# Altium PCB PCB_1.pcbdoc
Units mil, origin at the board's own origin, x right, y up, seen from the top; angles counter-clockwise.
Board outline 1920 x 3860 mil, 2 copper layers (Top Layer, Bottom Layer); 60 components, 43 nets, 203 pads, 40 vias.
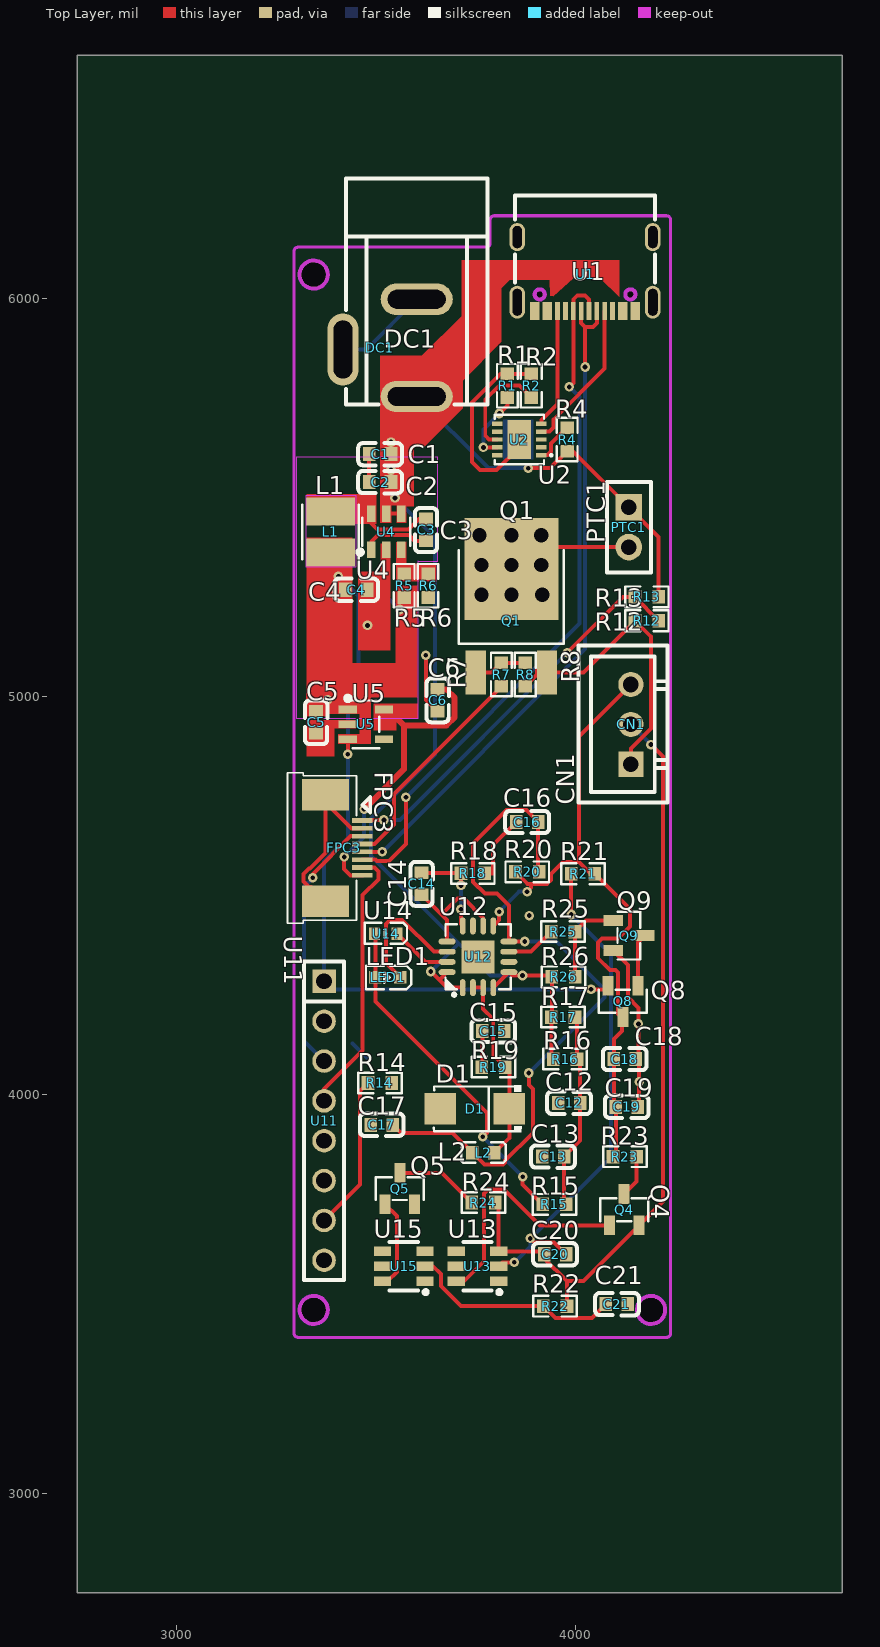
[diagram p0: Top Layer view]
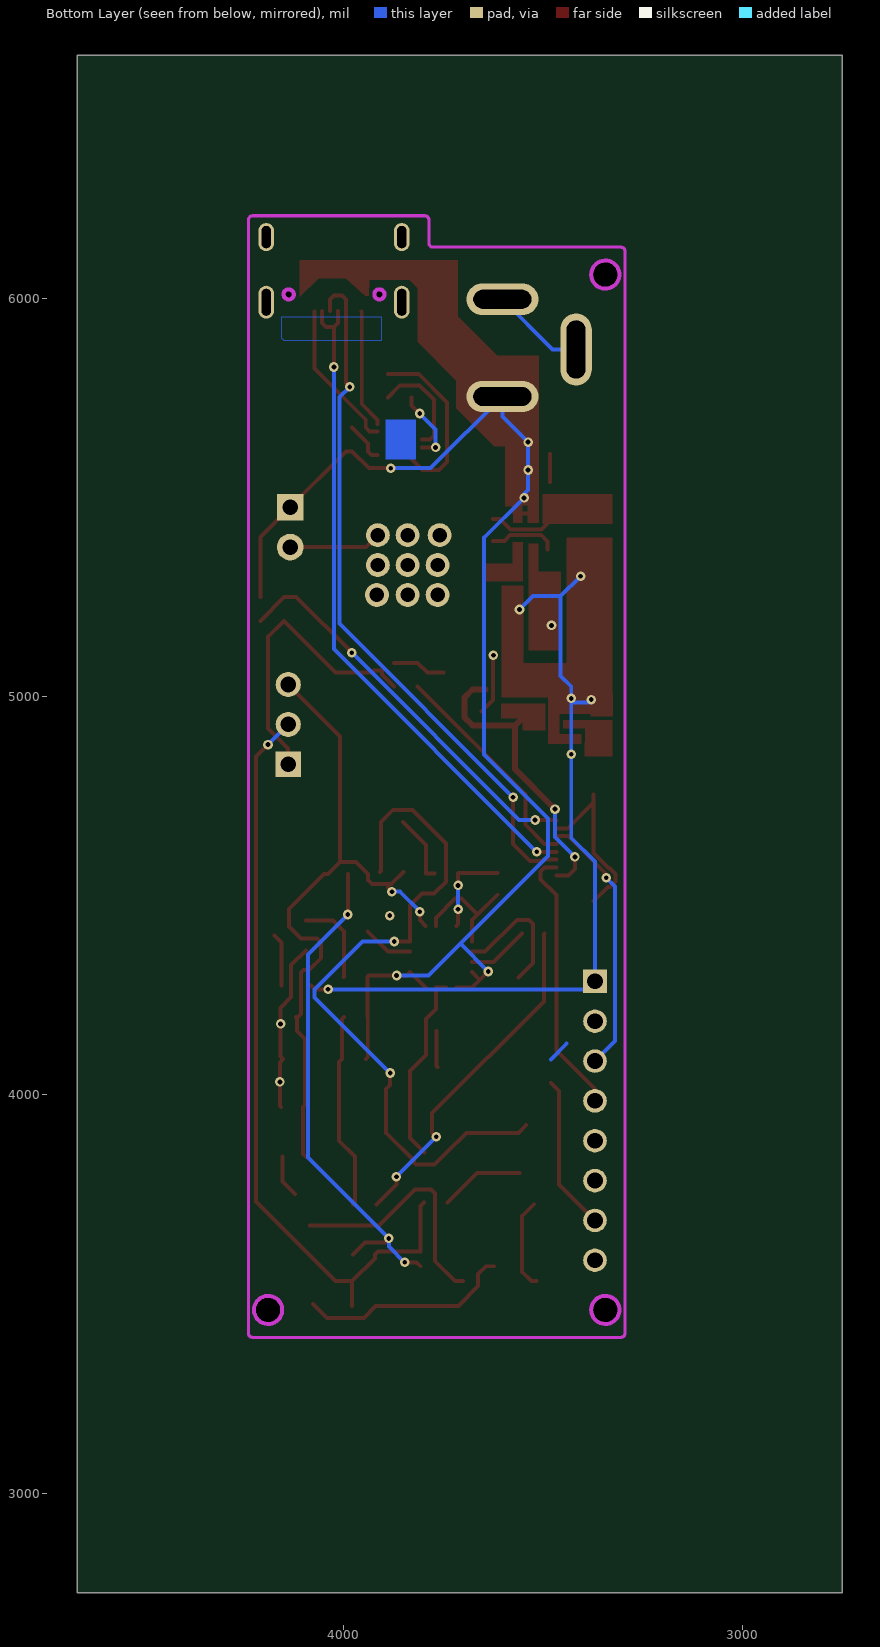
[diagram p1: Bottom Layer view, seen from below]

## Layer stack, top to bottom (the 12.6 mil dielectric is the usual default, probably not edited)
Top Layer: signal copper (thickness not stored)
Dielectric: dielectric 12.6, FR-4, Dk 4.8
Bottom Layer: signal copper (thickness not stored)

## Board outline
4670,2750 2750,2750 2750,6610 4670,6610
cut-out: 3379.43,6058.89 ccw(c3344,6058.67) 3308.57,6058.89 ccw(c3344,6059.11)
cut-out: 3379.43,3460.47 ccw(c3344,3460.25) 3308.57,3460.47 ccw(c3344,3460.69)
cut-out: 4225.89,3460.47 ccw(c4190.45,3460.47) 4155.02,3460.47 ccw(c4190.45,3460.47)

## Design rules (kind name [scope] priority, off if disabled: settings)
BoardOutlineClearance copperThickness1oz [All] p0: genericclearance=10 ignorepadtopadclearanceinfootprint=FALSE except(0: Arc-SplitContinuation Track-SplitContinuation SMDPad-SplitContinuation THPad-SplitContinuation Via-SplitContinuation Fill-SplitContinuation Poly-SplitContinuation Region-SplitContinuation Text-SplitContinuation; 6: Track-CutoutEdge SMDPad-CutoutEdge THPad-CutoutEdge Via-CutoutEdge Region-CutoutEdge; 11.8: Track-OutlineEdge SMDPad-OutlineEdge THPad-OutlineEdge Via-OutlineEdge Fill-OutlineEdge Region-OutlineEdge Poly-OutlineEdge Text-OutlineEdge Fill-CutoutEdge)
BoardOutlineClearance copperThickness2oz [All] p0: genericclearance=10 ignorepadtopadclearanceinfootprint=FALSE except(0: Arc-SplitContinuation Track-SplitContinuation SMDPad-SplitContinuation THPad-SplitContinuation Via-SplitContinuation Fill-SplitContinuation Poly-SplitContinuation Region-SplitContinuation Text-SplitContinuation; 6: Track-CutoutEdge SMDPad-CutoutEdge THPad-CutoutEdge Via-CutoutEdge Region-CutoutEdge; 11.8: Track-OutlineEdge SMDPad-OutlineEdge THPad-OutlineEdge Via-OutlineEdge Fill-OutlineEdge Region-OutlineEdge Poly-OutlineEdge Text-OutlineEdge Fill-CutoutEdge)
Clearance copperThickness1oz [(InNet('GND') OR InNet('3V3') OR InNet('ADC_VIN') OR InNet('$2N1457') OR InNet('$2N1458') OR InNet('VIN') OR InNet('5V') OR InNet('DN1') OR InNet('DP1') OR InNet('$2N173') OR InNet('$2N169') OR InNet('$2N860') OR InNet('$2N846') OR InNet('$2N1461') OR InNet('$2N861') OR InNet('CC1') OR InNet('CC2') OR InNet('PTC') OR InNet('SCL') OR InNet('SDA') OR InNet('AD0') OR InNet('XDA') OR InNet('XCL') OR InNet('INT') OR InNet('$2N25200') OR InNet('$2N24838') OR InNet('$2N25111') OR InNet('$2N25373') OR InNet('$2N25939') OR InNet('BAT+') OR InNet('$2N25975') OR InNet('$2N28041') OR InNet('$2N26224') OR InNet('$2N25852') OR InNet('$2N24540') OR InNet('$2N24753') OR InNet('$2N26433') OR InNet('$2N26509') OR InNet('$2N26582') OR InNet('$2N26578') OR InNet('$2N27775') OR InNet('$2N27867') OR InNet('$2N26613'))] p1: gap=7 ignorepadtopadclearanceinfootprint=FALSE except(4: Track-Track; 6: Track-SMDPad SMDPad-SMDPad Track-THPad SMDPad-THPad THPad-THPad Track-Via SMDPad-Via THPad-Via Via-Via SMDPad-Fill THPad-Fill Via-Fill Fill-Fill Track-Region SMDPad-Region THPad-Region Via-Region Region-Region Track-Poly SMDPad-Poly THPad-Poly Via-Poly Fill-Poly Region-Poly Poly-Poly Track-Text SMDPad-Text THPad-Text Via-Text Fill-Text Region-Text Poly-Text Text-Text; 6.9: Track-Hole SMDPad-Hole THPad-Hole Via-Hole Fill-Hole Region-Hole Poly-Hole Text-Hole Sheet-Hole; 11.8: Track-Fill Fill-Region Track-Sheet SMDPad-Sheet THPad-Sheet Via-Sheet Fill-Sheet Region-Sheet Poly-Sheet Text-Sheet)
Clearance copperThickness2oz [All] p1: gap=7 ignorepadtopadclearanceinfootprint=FALSE except(6: Track-SMDPad SMDPad-SMDPad Track-THPad SMDPad-THPad THPad-THPad Track-Via SMDPad-Via THPad-Via Via-Via SMDPad-Fill THPad-Fill Via-Fill Fill-Fill Track-Region SMDPad-Region THPad-Region Via-Region Region-Region Track-Poly SMDPad-Poly THPad-Poly Via-Poly Fill-Poly Region-Poly Poly-Poly Track-Text SMDPad-Text THPad-Text Via-Text Fill-Text Region-Text Poly-Text Text-Text; 6.9: Track-Hole SMDPad-Hole THPad-Hole Via-Hole Fill-Hole Region-Hole Poly-Hole Text-Hole Sheet-Hole; 8: Track-Track; 11.8: Track-Fill Fill-Region Track-Sheet SMDPad-Sheet THPad-Sheet Via-Sheet Fill-Sheet Region-Sheet Poly-Sheet Text-Sheet)
DiffPairsRouting differentialPair [All] p1: maxuncoupledlength=10 minlimit=6 maxlimit=6 mostfreqgap=6 toplayer_minwidth=5 toplayer_prefwidth=10 toplayer_maxwidth=100 bottomlayer_minwidth=5 bottomlayer_prefwidth=10 bottomlayer_maxwidth=100
PasteMaskExpansion pasteMaskExpansion [All] p1: expansion=0
PlaneConnect innerPlane [All] p1: planeconnectstyle=Relief reliefexpansion=20 reliefentries=4 reliefconductorwidth=10 reliefairgap=10
PolygonConnect copperRegion [All] p1: connectstyle=Relief reliefentries=4 reliefconductorwidth=10 polygonreliefangle="90 Angle" airgapwidth=10
RoutingVias viaSize [All] p1: viastyle="Through Hole" holewidth=12.0078 minholewidth=11.811 maxholewidth=248.0314 width=24.0158 minwidth=19.685 maxwidth=393.7008
SolderMaskExpansion solderMaskExpansion [All] p1: useseparateexpansions=TRUE expansion=2 expansionbottom=2
Width copperThickness1oz [All] p1: maxlimit=100 minlimit=5 preferedwidth=10
Width copperThickness2oz [All] p1: maxlimit=100 minlimit=8 preferedwidth=10

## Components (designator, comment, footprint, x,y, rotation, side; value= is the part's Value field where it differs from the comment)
C1 "CGA0603X7R104K500JT" C0603 3510.47,5608.23 r180 top
C2 "CL10A106KP8NNNC" C0603 3510.47,5538.23 r180 top
C3 "CGA0603X7R104K500JT" C0603 3626.08,5418.01 r90 top
C4 "CGA0603X7R104K500JT" C0603 3451.08,5268.01 r0 top
C5 "CGA0603X7R104K500JT" C0603 3350,4935 r270 top
C6 "CL10A106KP8NNNC" C0603 3655,4990 r270 top
C12 "CAP_0603" C0603 3985,3980 r0 top
C13 "CAP_0603" C0603 3945,3845 r0 top
C14 "CAP_0603" C0603 3615,4530 r90 top
C15 "CAP_0603" C0603 3795,4160 r0 top
C16 "CAP_0603" C0603 3880,4685 r0 top
C17 "CAP_0603" C0603 3515,3925 r0 top
C18 "CAP_0603" C0603 4125,4090 r0 top
C19 "CAP_0603" C0603 4130,3970 r0 top
C20 "CAP_0603" C0603 3950,3600 r0 top
C21 "CAP_0603" C0603 4105,3475 r180 top
CN1 "ZX-XH2.54-3PZZ" CONN-TH_3P-P2.54_2501S-3P 4140,4930 r90 top
D1 "SS34_C8678" SMA_L4.3-W2.6-LS5.2-RD 3748.22,3965 r180 top
DC1 "DC005" DC-IN-TH_DC005 3510,5875 r270 top locked
FPC3 "F0501-T-08-20T-R" FPC-SMD_8P-P0.50_L4.4-W9.6 3420,4620 r270 top
L1 "CD32-4R7M 4.7UH" IND-SMD_L3.5-W3.0 3386.08,5413.01 r90 top
L2 "L_0603" l0603 3770,3855 r0 top
LED1 "XL-1608SURC-06" LED0603-RD_RED 3530,4295 r180 top
PTC1 "HDR-F_2.54_1x2P" HDR-TH_2P-P2.54-V-F 4135,5425 r270 top
Q1 "AOD4184L" TO-252-2_L6.6-W6.1-P4.57-LS9.9-TL-CW 3840,5190 r90 top
Q4 "SI2302_C2891732" SOT-23-3_L2.9-W1.3-P1.90-LS2.4-BR 4123.23,3711.97 r270 top
Q5 "SI2302_C2891732" SOT-23-3_L2.9-W1.3-P1.90-LS2.4-BR 3560,3765 r270 top
Q8 "IRLML6402_C518785" SOT-23-3_L2.9-W1.3-P1.90-LS2.4-BR 4120,4235 r90 top
Q9 "MMBT3904(RANGE:100-300)" SOT-23-3_L2.9-W1.3-P1.90-LS2.4-BR 4135,4400 r180 top
R1 "0603WAF1002T5E" R0603 3830,5780 r90 top
R2 "0603WAF1002T5E" R0603 3890,5780 r90 top
R4 "0603WAF100JT5E" R0603 3980,5645 r270 top
R5 "FRC0603F2703TS" R0603 3571.08,5278.01 r270 top
R6 "0603WAF5102T5E" R0603 3631.08,5278.01 r90 top
R7 "0603WAF1000T5E" R0603 3815,5055 r90 top
R8 "0603WAF1002T5E" R0603 3875,5055 r270 top
R12 "0603WAF5102T5E" R0603 4180,5190 r180 top
R13 "0603WAF2703T5E" R0603 4180,5250 r180 top
R14 "Res_0603" R0603 3510,4030 r180 top
R15 "Res_0603" R0603 3948.31,3725.44 r0 top
R16 "Res_0603" R0603 3975,4090 r0 top
R17 "Res_0603" R0603 3969.99,4195.44 r0 top
R18 "Res_0603" R0603 3743.31,4555.95 r0 top
R19 "Res_0603" R0603 3795,4070 r180 top
R20 "Res_0603" R0603 3880,4560 r0 top
R21 "Res_0603" R0603 4020,4555 r0 top
R22 "Res_0603" R0603 3950,3470 r0 top
R23 "Res_0603" R0603 4125,3845 r180 top
R24 "Res_0603" R0603 3770,3730 r0 top
R25 "Res_0603" R0603 3970,4410 r180 top
R26 "Res_0603" R0603 3971.2,4296.3 r0 top
U1 "TYPE-C16PIN" USB-C-SMD_TYPE-C16PIN 4025,6060 r180 top
U2 "HUSB238_002DD" DFN-10_L3.0-W3.0-P0.50-BL-EP2.5 3860,5645 r90 top
U4 "RY8411_C2935411" SOT-23-6_L2.9-W1.6-P0.95-LS2.8-TL 3526.14,5413.63 r90 top
U5 "ME6212C33M5G" SOT-23-5_L3.0-W1.7-P0.95-LS2.8-BL 3475,4930 r270 top
U11 "HB-PH3-25418PB2GOP" HDR-TH_8P-P2.54-V-M 3370,3935 r270 top
U12 "TP5100" TQFN-16_L4.0-W4.0-P0.65-BL-EP 3756.45,4346.68 r0 top
U13 "HY2213-BB3A" SOT-23-6_L2.9-W1.6-P0.95-LS2.8-BR 3755,3570 r0 top
U14 "42-51/GHC-YW2X2K/3T" LED-SMD_L1.6-W0.8-FD_GREEN-1 3525,4405 r0 top
U15 "HY2213-BB3A" SOT-23-6_L2.9-W1.6-P0.95-LS2.8-BR 3570,3570 r0 top

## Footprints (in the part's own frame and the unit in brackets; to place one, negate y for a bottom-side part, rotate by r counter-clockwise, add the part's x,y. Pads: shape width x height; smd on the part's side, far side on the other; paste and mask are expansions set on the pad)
C0603 [mm]
  rect 0.8x0.9 smd: 1(-0.7,0) 2(0.7,0)
  silkscreen extent -1.41,-0.71 1.39,0.72
CONN-TH_3P-P2.54_2501S-3P [mm]
  rect 1.6x1.6 hole 1: 1(-2.54,0)
  round 1.6 hole 1: 2(0,0) 3(2.54,0)
  silkscreen extent -4.98,-2.35 5.02,3.35
DC-IN-TH_DC005 [mm]
  oval 2x4.6 hole 1.2 slot 3.7 at 90 deg: 1(3.1,2.35) 2(-3.1,2.35)
  oval 4.6x2 hole 1.2 slot 3.7 at 0 deg: 3(0.1,-2.35)
  silkscreen extent -10.8,-2.15 3.6,6.85
DFN-10_L3.0-W3.0-P0.50-BL-EP2.5 [mm]
  rect 0.28x0.665 smd: 1(-1,-1.407) 2(-0.5,-1.407) 3(0,-1.407) 4(0.5,-1.407) 5(1,-1.407) 6(1,1.407) 7(0.5,1.407) 8(0,1.407) 9(-0.5,1.407) 10(-1,1.407)
  rect 2.5x1.5 smd: 11(0,0)
  silkscreen extent -1.58,-2.12 1.58,1.58
FPC-SMD_8P-P0.50_L4.4-W9.6 [mm]
  rect 2x3 smd: 0(-3.4,-1.175) 0(3.4,-1.175)
  rect 0.3x1.3 smd: 1(-1.75,1.175) 2(-1.25,1.175) 3(-0.75,1.175) 4(-0.25,1.175) 5(0.25,1.175) 6(0.75,1.175) 7(1.25,1.175) 8(1.75,1.175)
  silkscreen extent -4.8,-3.6 4.8,1.68
HDR-TH_2P-P2.54-V-F [mm]
  rect 1.7x1.7 hole 1: 1(-1.27,0)
  round 1.7 hole 1: 2(1.27,0)
  silkscreen extent -2.88,-1.39 2.88,1.4
HDR-TH_8P-P2.54-V-M [mm]
  rect 1.5x1.5 hole 1: 1(-8.89,0)
  round 1.5 hole 1: 2(-6.35,0) 3(-3.81,0) 4(-1.27,0) 5(1.27,0) 6(3.81,0) 7(6.35,0) 8(8.89,0)
  silkscreen extent -10.16,-1.27 10.16,1.27
IND-SMD_L3.5-W3.0 [mm]
  rect 1.8x3.12 smd: 1(1.303,0) 2(-1.303,0)
  silkscreen extent -1.75,-1.8 1.75,1.8
l0603 [mm]
  rect 0.8x0.864 smd: 1(-0.7,0) 2(0.7,0)
  silkscreen extent -1.42,-0.65 1.41,0.67
LED0603-RD_RED [mm]
  rect 0.8x0.8 smd: 1(-0.8,-0.003) 2(0.8,0.003)
  silkscreen extent -1.49,-0.75 1.39,0.76
LED-SMD_L1.6-W0.8-FD_GREEN-1 [mm]
  rect 0.7x0.8 smd: 1(-0.715,0) 2(0.715,0)
  silkscreen extent -1.35,-0.65 1.35,0.7
R0603 [mil]
  rect 31.75x34.02 smd: 1(-29.66,0) 2(29.66,0)
  silkscreen extent -55,-26 55,26
SMA_L4.3-W2.6-LS5.2-RD [mm]
  rect 2x2 smd: 1(-2.2,0) 2(2.2,0)
  silkscreen extent -2.98,-1.5 2.6,1.5
SOT-23-3_L2.9-W1.3-P1.90-LS2.4-BR [mm]
  rect 1.25x0.7 smd: 1(1,-0.95) 2(1,0.95) 3(-1,0)
  silkscreen extent -0.73,-1.53 0.73,1.53
SOT-23-5_L3.0-W1.7-P0.95-LS2.8-BL [mm]
  rect 0.49x1.157 smd: 1(-0.95,-1.154) 2(0,-1.154) 3(0.95,-1.154)
  rect 0.49x1.175 smd: 4(0.95,1.154) 5(-0.95,1.154)
  silkscreen extent -1.8,-1.29 1.53,0.85
SOT-23-6_L2.9-W1.6-P0.95-LS2.8-BR [mm]
  rect 1.1x0.6 smd: 1(1.35,-0.95) 2(1.35,0) 3(1.35,0.95) 4(-1.35,0.95) 5(-1.35,0) 6(-1.35,-0.95)
  silkscreen extent -0.9,-1.78 1.52,1.55
SOT-23-6_L2.9-W1.6-P0.95-LS2.8-TL [mil]
  rect 42.2x20.95 smd: 1(-45.24,37.4) 2(-45.24,0) 3(-45.24,-37.4) 4(45.24,-37.4) 5(45.24,0) 6(45.24,37.4)
  silkscreen extent -57,-61 35,72
TO-252-2_L6.6-W6.1-P4.57-LS9.9-TL-CW [mm]
  rect 2.8x1.3 smd: 1(-3.292,2.273) 3(-3.292,-2.273)
  rect 6.5x6 smd: 2(3.292,0)
  silkscreen extent -1.46,-3.35 4.51,3.34
TQFN-16_L4.0-W4.0-P0.65-BL-EP [mil]
  oval 14.33x42.8 smd: 1(-38.39,-77.5) 2(-12.79,-77.5) 3(12.8,-77.5) 4(38.39,-77.5) 9(38.39,77.5) 10(12.8,77.5) 11(-12.79,77.5) 12(-38.39,77.5)
  oval 42.8x14.33 smd: 5(77.5,-38.39) 6(77.5,-12.8) 7(77.5,12.79) 8(77.5,38.39) 13(-77.5,38.39) 14(-77.5,12.79) 15(-77.5,-12.8) 16(-77.5,-38.39)
  rect 82.68x82.68 smd: 17(0,0)
  silkscreen extent -82,-99 82,82
USB-C-SMD_TYPE-C16PIN [mm]
  oval 1x2.1 hole 0.6 slot 1.7 at 90 deg: 1(-4.32,1.787) 2(4.32,1.787)
  oval 1x1.8 hole 0.6 slot 1.4 at 90 deg: 3(-4.32,-2.362) 4(4.32,-2.362)
  rect 0.6x1.15 smd: A1B12(-3.2,2.362) A4B9(-2.4,2.362) B1A12(3.2,2.362) B4A9(2.4,2.362)
  rect 0.3x1.15 smd: A5(-1.25,2.362) A6(-0.25,2.362) A7(0.25,2.362) A8(1.25,2.362) B5(1.75,2.362) B6(0.75,2.362) B7(-0.75,2.362) B8(-1.75,2.362)
  Board Outline Layer circle w0.005: c2.89,1.288 r0.325
  Board Outline Layer circle w0.005: c-2.89,1.288 r0.325
  Board Outline Layer circle w0.254: c2.89,1.288 r0.325
  Board Outline Layer circle w0.254: c-2.89,1.288 r0.325
  Multi-Layer board cut-out: 2.565,1.288 2.611,1.128 2.729,1.012 2.89,0.969 3.051,1.012 3.169,1.128 3.215,1.288 3.215,1.288 3.169,1.448 3.051,1.564 2.89,1.607 2.729,1.564 2.611,1.448 2.565,1.288
  Multi-Layer board cut-out: -3.215,1.288 -3.183,1.147 -3.093,1.034 -2.962,0.971 -2.818,0.971 -2.687,1.034 -2.597,1.147 -2.565,1.288 -2.565,1.288 -2.597,1.429 -2.687,1.542 -2.818,1.605 -2.962,1.605 -3.093,1.542 -3.183,1.429 -3.215,1.288
  silkscreen extent -4.45,-5 4.45,0.52

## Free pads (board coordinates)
  round 60 hole 36: 1(3760,5405) 2(3840.26,5405) 3(3915,5405) 4(3765,5330) 5(3840.26,5330) 6(3915,5330) 7(3765,5255) 8(3840.26,5255) 9(3917.33,5255)

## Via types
v1: diameter 24.02, hole 12.01, Top Layer to Bottom Layer, 40 vias

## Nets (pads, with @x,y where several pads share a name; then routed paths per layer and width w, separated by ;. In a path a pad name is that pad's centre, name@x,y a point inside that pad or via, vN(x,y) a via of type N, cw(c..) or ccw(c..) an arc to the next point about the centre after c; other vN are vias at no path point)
3V3: C6.1 FPC3.8 U5.5 | length 787.7
  Top Layer w10: v1(3420.42,4597.4) 3420.42,4567.4 3436.72,4551.1 FPC3.8
  Top Layer w15: v1(3470.42,4717.4) 3570.42,4817.4 3570.42,4927.4 ; U5.5 3530.42,4967.4 3570.42,4927.4 ; C6.1@3645,5017.56 3677.44,5017.56 3697.79,4997.21 3697.79,4947.79 3677.4,4927.4 3570.42,4927.4
  Bottom Layer w10: v1(3420.42,4597.4) 3470.42,4647.4 v1(3470.42,4717.4)
5V: C4.1 C5.1 L1.2 Q8.2 R5.2 U5.1 U5.3 U11.1 | length 2219.5
  Top Layer w10: C5.1 v1(3379.58,4992.14) ; v1(3429.58,4855.21) U5.3 ; U5.1 v1(3429.58,4995.21) ; v1(4040,4265) 4073.23,4265 Q8.2
  Top Layer w20: L1.2 3406.08,5341.71 3406.08,5291.71 3423.52,5274.27 C4.1 ; v1(3559.44,5218.35) 3559.44,5238.35 R5.2
  Bottom Layer w10: v1(3379.58,4992.14) 3386.51,4985.21 v1@3429.58,4985.21 ; v1(3406.08,5301.71) 3456.08,5251.71 ; v1(3559.44,5218.35) 3526.08,5251.71 3456.08,5251.71 ; v1(4040,4265) 3390,4265 U11.1 3370,4585.63 3429.58,4645.21 v1(3429.58,4855.21) v1@3429.58,4985.21 ; v1@3429.58,4985.21 v1(3429.58,4995.21) 3429.58,5025.21 3456.08,5051.71 3456.08,5251.71
$2N169: Q1.1 R7.2 R8.1 | length 134.5
  Top Layer w10: Q1.1 3790.74,5060.4 R7.2 R8.1
$2N173: pad.1 pad.2 pad.3 pad.4 pad.5 pad.6 pad.7 pad.8 pad.9 PTC1.2 Q1.2 | length 232.4
  Top Layer w10: pad.3 3945,5375 PTC1.2
$2N846: R4.1 U2.1 | length 104.9
  Top Layer w9.92: U2.1 3930.97,5605.63 3940,5614.66 3940,5634.66 R4.1
$2N860: R1.1 U2.9 | length 184.5
  Top Layer w9.92: v1(3770,5625.32) U2.9 ; v1(3810,5710.34) 3830,5730.34 R1.1
  Bottom Layer w9.92: v1(3770,5625.32) 3770,5670.34 v1(3810,5710.34)
$2N861: R2.1 U2.8 | length 266.6
  Top Layer w9.92: U2.8 3784.52,5645 3774.59,5654.93 3774.59,5744.93 3810,5780.34 3860,5780.34 R2.1
$2N1457: C3.2 L1.1 U4.6 | length 178.9
  Top Layer w10: U4.6 3488.74,5434.63 3504.2,5419.17 3582.39,5419.17 3608.79,5445.57 C3.2
$2N1458: C3.1 U4.1 | length 170.3
  Top Layer w10: U4.1 3488.74,5388.69 3504.87,5404.82 3583.04,5404.82 3597.41,5390.45 C3.1
$2N1461: R5.1 R6.2 U4.3 | length 123.8
  Top Layer w10: U4.3 3563.54,5318.39 3571.08,5310.85 R5.1 R6.2
$2N24540: LED1.1 U12.14 | length 339.5
  Top Layer w10: LED1.1 3525.82,4330.8 3525.82,4429.47 3535.82,4439.47 3565.82,4439.47 3645.82,4359.47 U12.14
$2N24753: LED1.2 R15.1 U14.1 | length 862.6
  Top Layer w10: U14.1 3498.52,4403.33 LED1.2 3498.52,4234.86 3778.52,3954.86 3778.52,3904.86 v1(3768.52,3894.86) ; v1(3868.52,3794.86) 3868.52,3775.57 R15.1
  Bottom Layer w10: v1(3768.52,3894.86) v1(3868.52,3794.86)
$2N24838: C12.2 C13.2 R15.2 R16.2 R17.2 | length 494.2
  Top Layer w10: R15.2 3972.56,3730.85 C13.2 4012.56,3885 C12.2 4012.56,4082.1 R16.2 4004.66,4190.44 R17.2
$2N25111: C14.2 R18.1 U12.12 | length 232.9
  Top Layer w10: C14.2 3712.03,4557.56 R18.1 v1(3713.65,4525.95) ; v1(3713.65,4465.95) 3713.65,4428.59 U12.12
  Bottom Layer w10: v1(3713.65,4465.95) v1(3713.65,4525.95)
$2N25200: C14.1 U12.10 U12.13 | length 304.7
  Top Layer w10: C14.1 3665,4452.44 ; U12.13 3678.95,4438.49 3665,4452.44 ; U12.10 3769.25,4444.18 3720.99,4492.44 3705,4492.44 3665,4452.44
$2N25373: C15.1 R19.2 | length 90.9
  Top Layer w10: R19.2 3767.44,4072.1 C15.1
$2N25852: D1.1 L2.2 R19.1 U12.2 U12.3 | length 482.4
  Top Layer w10: U12.2 U12.3 3769.25,4215.41 3794.66,4190 3794.66,4100 R19.1 3834.83,4059.83 D1.1 3834.83,3892.28 L2.2
$2N25939: C16.2 C17.2 L2.1 R20.2 U12.8 | length 1799.2
  Top Layer w10: C17.2 3562.56,3905 3692.45,3905 L2.1 3772.45,3825 3818.95,3825 3823.95,3830 3823.95,3835 3893.95,3905 3893.95,4015.07 3883.95,4025.07 v1(3883.95,4055.07) ; v1(3873.95,4385.06) U12.8 3833.95,4475 3803.95,4505 3773.95,4505 3743.95,4535 3743.95,4631.39 3827.56,4715 3877.56,4715 C16.2 3907.56,4562.1 R20.2
  Bottom Layer w10: v1(3873.95,4385.06) 3953.95,4385.06 4073.95,4265.06 4073.95,4245.06 v1(3883.95,4055.07)
$2N25975: C20.2 R21.1 U13.2 | length 1267.1
  Top Layer w10: U13.2 3818.15,3580 v1(3847.56,3580) ; v1(3887.56,3640) 3897.56,3630 3947.56,3630 C20.2 ; v1(3990.34,4452.78) R21.1
  Bottom Layer w10: v1(3847.56,3580) 3887.56,3620 v1(3887.56,3640) 4090.34,3842.78 4090.34,4352.78 v1(3990.34,4452.78)
$2N26224: C21.2 R22.1 U15.2 | length 540.2
  Top Layer w10: U15.2 3643.15,3570 3663.15,3550 3663.15,3520 3713.15,3470 R22.1 3950.34,3440 4042.44,3440 C21.2
$2N26433: Q4.1 U13.6 | length 616.1
  Top Layer w10: U13.6 3721.85,3532.6 3771.85,3582.6 3771.85,3752.6 3781.85,3762.6 3821.85,3762.6 3911.85,3672.6 Q4.1
$2N26509: Q4.3 R23.1 | length 106.7
  Top Layer w10: Q4.3 4154.66,3782.77 R23.1
$2N26578: Q5.3 R24.1 | length 211.1
  Top Layer w10: Q5.3 3665.97,3804.37 R24.1
$2N26582: Q5.1 U15.6 | length 227.7
  Top Layer w10: U15.6 3529.57,3532.6 3552.6,3555.63 3552.6,3695.63 Q5.1
$2N26613: U12.15 U14.2 | length 155.3
  Top Layer w10: U14.2 3624.28,4333.88 U12.15
$2N27775: Q8.1 Q9.3 | length 132.7
  Top Layer w10: Q8.1 4157.4,4383.03 Q9.3
$2N27867: Q9.1 R25.1 R26.2 | length 221.5
  Top Layer w10: R26.2 3999.66,4297.5 R25.1 4027.06,4437.4 Q9.1
$2N28041: C20.1 CN1.2 Q4.2 R22.2 R24.2 U13.3 | length 1951.7
  Top Layer w10: R24.2 3808.15,3721.51 U13.3 3915.04,3607.4 C20.1 3922.44,3590 3979.66,3532.78 ; R22.2 3979.66,3532.78 ; v1(4190.63,4879.38) 4220.63,4849.38 4220.63,3732.6 Q4.2 4020.81,3532.78 3979.66,3532.78
  Bottom Layer w10: CN1.2 v1(4190.63,4879.38)
AD0: R14.2 U11.7 | length 390.7
  Top Layer w10: U11.7 3460,3775 3460,4009.66 R14.2
ADC_VIN: FPC3.1 R12.1 R13.2 | length 1001.1
  Top Layer w10: FPC3.1 3467.36,4690 v1(3520.34,4690) ; v1(3980.34,5110) 4120.34,5250 R13.2 4150.34,5249.32 R12.1
  Bottom Layer w10: v1(3520.34,4690) 3560.34,4690 v1(3980.34,5110)
BAT+: C18.1 C19.1 CN1.3 Q8.3 R20.1 R21.2 R23.2 U12.9 | length 1764.6
  Top Layer w10: U12.9 3809.66,4438.99 v1(3809.66,4460) ; R20.1 3880.34,4530 3889.66,4530 ; v1(3879.66,4510) 3889.66,4520 3889.66,4530 ; R23.2 4102.44,3852.1 C19.1 4097.44,3975 C18.1 4097.44,4140 4117.44,4160 Q8.3@4117.44,4193.07 ; Q8.3 Q8.3@4117.44,4193.07 ; CN1.3 4009.66,4899.65 4009.66,4585 ; 3889.66,4530 3929.66,4530 3939.66,4540 3939.66,4555 3969.66,4585 4009.66,4585 ; 4009.66,4585 4039.66,4555 R21.2 4137.44,4467.22 4137.44,4423.07 4107.44,4393.07 4067.44,4393.07 4057.44,4383.07 4057.44,4343.07 4087.44,4313.07 4101.67,4313.07 4107.44,4307.3 4107.44,4203.07 Q8.3@4117.44,4193.07
  Bottom Layer w10: v1(3809.66,4460) 3859.66,4510 v1(3879.66,4510)
CC1: U1.A5 U2.4 | length 379.8
  Top Layer w9.92: U2.4 3935.41,5664.69 3945.41,5674.69 3945.41,5694.69 4074.21,5823.49 U1.A5
CC2: U1.B5 U2.5 | length 299.5
  Top Layer w9.92: U2.5 3915.41,5694.37 3955.41,5734.37 3955.41,5966.3 U1.B5
DN1: FPC3.5 U1.A7 U1.B7 | length 1686.2
  Top Layer w10: FPC3.5 v1(3516.26,4610.15) ; U1.A7 4015.16,5936.99 4025.16,5926.99 ; v1(4025.16,5826.99) 4025.16,5926.99 ; U1.B7 4055.16,5966.36 4055.16,5936.99 4045.16,5926.99 4025.16,5926.99
  Bottom Layer w10: v1(3516.26,4610.15) 4025.16,5119.06 v1(4025.16,5826.99)
DP1: FPC3.6 U1.A6 U1.B6 | length 1769.4
  Top Layer w10: FPC3.6 3499.29,4590.48 3502.78,4586.99 3532.78,4586.99 3575.47,4629.69 v1(3575.47,4746.99) ; v1(3985.47,5776.99) 3995.47,5786.99 U1.B6 3995.47,5996.99 4005.47,6006.99 4025.47,6006.99 4035.47,5996.99 4035.47,5967.62 U1.A6
  Bottom Layer w10: v1(3575.47,4746.99) 4011.14,5182.66 4011.14,5751.32 v1(3985.47,5776.99)
GND: C1.2 C2.2 C4.2 C5.2 C6.2 C12.1 C13.1 C15.2 C16.1 C17.1 C18.2 C19.2 C21.1 CN1.1 D1.2 DC1.2 DC1.3 FPC3.0 FPC3.2 Q1.3 Q5.2 Q9.2 R1.2 R2.2 R6.1 R8.2 R12.2 R14.1 R18.2 R25.2 U2.11 U4.2 U5.2 U11.2 U12.7 U15.3 | length 2932.9
  Top Layer w10: FPC3.0@3373.74,4486.15 3337.88,4522.01 3332.21,4522.01 3318.74,4535.48 3318.74,4554.52 3332.21,4567.99 3334.91,4567.99 3373.74,4606.83 FPC3.0@3373.74,4733.85 ; FPC3.0@3373.74,4753.85 FPC3.0@3373.74,4733.85 ; FPC3.2 3438.38,4669.22 FPC3.0@3373.74,4733.85 ; C2.2 C1.2 ; v1(3625.04,5103.35) 3626.3,5102.09 3626.3,4991.14 C6.2 ; R18.2 3794.39,4555.95 3794.39,4626.95 C16.1 ; U12.7 3889.8,4359.47 R25.2 ; U2.11 3860,5625 3803.35,5568.35 3761.08,5568.35 3741.08,5588.35 3741.08,5738.35 3812.39,5809.66 R1.2 R2.2 ; R8.2 3905,5055.34 3905,5065.34 3924.53,5065.34 Q1.3 4020.74,5060.4 R12.2 4190.34,5150 4190.34,4920 4139.99,4869.65 CN1.1 ; Q9.2 4132.64,4325.59 4132.64,4245.21 4159.11,4218.74 v1(4159.11,4178.35) 4159.11,4096.55 C18.2 4160.89,4081.67 v1(4160.89,4032.72) 4160.89,3973.33 C19.2
  Bottom Layer w10: DC1.3 3476.55,5871.06 DC1.2 ; 3440.92,4128.74 3480.92,4088.74
  other v1: 3885,4450 3479.11,5178.35
INT: U11.8
PTC: FPC3.4 R7.1 | length 557.5
  Top Layer w10: FPC3.4 3496.26,4629.85 3545,4678.59 3545,4755.34 R7.1
SCL: FPC3.3 U11.3 | length 663.4
  Top Layer w10: v1(3341.74,4545) 3341.74,4555 3436.26,4649.52 FPC3.3
  Bottom Layer w10: v1(3341.74,4545) 3320,4523.27 3320,4135 U11.3
SDA: FPC3.7 U11.4 | length 677
  Top Layer w10: U11.4 3370,4015 3466.26,4111.26 3466.26,4501.26 3506.26,4541.26 3506.26,4561.26 3496.26,4571.26 3466.74,4571.26 FPC3.7
VIN: C1.1 C2.1 DC1.1 PTC1.1 R4.2 R13.1 R16.1 R17.1 R26.1 U4.4 U4.5 U12.1 U12.4 U12.5 U12.16 | length 3433.7
  Top Layer w10: U4.5 U4.4 ; C2.1 v1(3538.03,5568.48) ; C1.1 v1(3538.03,5638.48) ; v1(3638.03,4309.81) 3658.03,4289.81 ; U12.16 3660.47,4289.81 3658.03,4289.81 ; U12.1 3678.66,4269.18 3658.03,4289.81 ; U12.4 U12.5 3842.43,4299.81 v1(3868.03,4299.81) 3938.03,4299.81 R26.1 3941.54,4196.65 R17.1 3940.33,4095.01 R16.1 ; v1(3882.51,5572.96) 3937.62,5572.96 R4.2 3994.66,5615.34 PTC1.1 4209.66,5400.34 R13.1
  Bottom Layer w10: v1(3638.03,4309.81) 3708.03,4379.81 ; v1(3868.03,4299.81) 3788.03,4299.81 3708.03,4379.81 ; v1(3882.51,5572.96) 3782.51,5572.96 DC1.1 3602.51,5702.96 v1(3538.03,5638.48) v1(3538.03,5568.48) 3538.03,5518.48 3548.03,5508.48 v1(3548.03,5498.48) 3648.03,5398.48 3648.03,4854.04 3488.03,4694.04 3488.03,4599.81 3708.03,4379.81
XCL: U11.6
XDA: U11.5
pads on no net: U1.1 U1.2 U1.3 U1.4 U1.A1B12 U1.A4B9 U1.A8 U1.B1A12 U1.B4A9 U1.B8 U2.2 U2.3 U2.6 U2.7 U2.10 U5.4 U12.6 U12.11 U12.17 U13.1 U13.4 U13.5 U15.1 U15.4 U15.5

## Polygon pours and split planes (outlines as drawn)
GND on Top Layer (solid, remove dead copper, pour order 0): 3030,6360 4420,6360 4420,3170 3030,3170
$2N173 on Bottom Layer (solid, remove dead copper, pour order 4): 3720,5610 4005,5610 cw(c4005,5600) 4015,5600 4015,5149.48 cw(c4005,5149.48) 4005,5139.48 3720,5139.48 cw(c3720,5149.48) 3710,5149.48 3710,5600 cw(c3720,5600)
GND on Bottom Layer (solid, remove dead copper, pour order 6): 3000,6190 4390,6190 4390,3000 3000,3000
VIN on Bottom Layer (solid, remove dead copper, pour order 2): 3904.92,5951.88 4156.89,5951.88 4156.89,5900.48 4150.98,5894.58 3905,5894.58 3904.92,5894.66

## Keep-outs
Top Layer:
  region: 3325,5505 3450,5505 3450,5325 3325,5325
  region: 3300,5600 3300,4945 3605.78,4945 3605.78,5339.22 3605,5340 3655,5340 3655,5600
Board Outline Layer:
  circle w1: c3344,6058.89 r35.43
  circle w10: c3344,6058.89 r35.43
  circle w1: c3344,3460.47 r35.43
  circle w10: c3344,3460.47 r35.43
  circle w1: c4190.46,3460.47 r35.43
  circle w10: c4190.46,3460.47 r35.43
  lines w7.87: 3294.79,3401.58 3294.79,6117.79 cw(c3304.79,6117.79) 3304.79,6127.79 3776.91,6127.79 ccw(c3776.91,6137.79) 3786.91,6137.79 3786.91,6196.53 cw(c3796.91,6196.53) 3796.91,6206.53 4229.67,6206.53 cw(c4229.67,6196.53) 4239.67,6196.53 4239.67,3401.58 cw(c4229.67,3401.58) 4229.67,3391.58 3304.79,3391.58 cw(c3304.79,3401.58) 3294.79,3401.58

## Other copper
Top Layer:
  region net $2N1457: 3326.08,5433.01 3326.08,5508.01 3501.08,5508.01 3501.08,5433.01
  region net $2N1461: 3551.08,5387.61 3576.08,5388.01 3576.08,5333.01 3652.09,5333.01 3652.09,5289.79 3551.08,5289.79
  region net VIN: 3511.17,5435.98 3511.17,5627.73 3510.78,5627.73 3510.78,5855 3615,5855 3715,5955 3715,6095 4110.98,6095 4110.98,6002.87 4063.77,6050 3995,6050 3945,6005 3937.56,6005.22 3936.42,6046.6 3836.6,6046.6 3815,6025 3815,5890 3717.98,5792.98 3717.98,5722.98 3622.73,5627.73 3594.82,5627.73 3594.82,5477.44 3576.04,5477.44 3575.67,5436.22 3552.75,5436.22 3552.99,5479.9 3538.36,5480 3538.36,5435.98
  region net 5V: 3325.85,5008.09 3326.08,5008.09 3326.08,5398.01 3441.08,5398.01 3441.08,5083.01 3549.71,5083.01 3549.71,5278.01 3603.49,5278.01 3603.49,4998.01 3486.91,4998.01 3486.91,4881.48 3405,4881.48 3405,4905 3459.89,4905 3459.89,4956.42 3380.25,4956.42 3380.25,4950.85 3325.85,4950.85
  region net GND: 3449.05,4940.38 3326.57,4940.31 3326.57,4849.64 3395.75,4849.64 3395,4920 3449.05,4920
  region net 3V3: 3495,4981.2 3495,4915 3550.97,4915 3550.97,4945.97 3605.45,4945.97 3605.45,4981.2
  region net GND: 3536.08,5383.01 3511.84,5383.01 3511.84,5313.01 3456.08,5313.01 3456.08,5115.78 3536.08,5115.78
Bottom Layer:
  region net GND: 3820,5695 3820,5595 3894.01,5595 3895.02,5596.01 3895.02,5695

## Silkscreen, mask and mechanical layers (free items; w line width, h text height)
Top Solder Mask Layer:
  region: 3915,5140.41 3713.52,5140 3713.52,5391.99 3771.53,5450 3985,5450 3985,5275 3915,5205
Bottom Solder Mask Layer:
  region: 3725,5395 3775,5445 3935,5445 3935,5220 3920,5205 3920,5195 3725,5195
Mechanical Layer:
  circle w1: c3344,6058.89 r35.43
  circle w1: c3344,3460.47 r35.43
  circle w1: c4190.46,3460.47 r35.43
